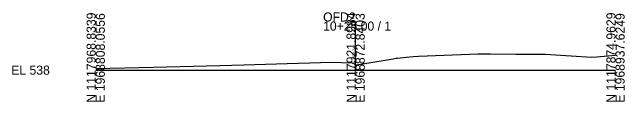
# Model space of a CAD drawing. Extents: x -26 to 163, y -10 to 2018.
# Drawn here: x -25.7 to 162.8, y -9.7 to 17.8 of the extents above; entities that cross this region are included whole.
import ezdxf

# ---------------------------------------------------------------- set-up
doc = ezdxf.new("R2010")
doc.units = 0
for name, color, linetype in [('RD_GPK_XS_Cell', 7, 'Continuous'), ('RD_XS_ExGround', 7, 'Continuous'), ('RD_XS_TX_Elev_EX', 7, 'Continuous')]:
    doc.layers.add(name, color=color, linetype=linetype)

msp = doc.modelspace()

# ---------------------------------------------------------------- linework, layer by layer
at = {"layer": 'RD_GPK_XS_Cell'}
for p, q in [((80, 0), (80, 14.92)), ((0, 0), (80, 0)), ((80, 0), (160, 0))]:
    msp.add_line(p, q, dxfattribs=at)
at = {"layer": 'RD_XS_ExGround'}
for p, q in [((92.89, 3.72), (95.58, 3.98)), ((95.58, 3.98), (97.74, 4.2)), ((97.74, 4.2), (99.39, 4.26)), ((99.39, 4.26), (117.73, 4.97)), ((117.73, 4.97), (121.49, 4.96)), ((121.49, 4.96), (129.28, 4.95)), ((129.28, 4.95), (131.76, 4.94)), ((131.76, 4.94), (132.93, 4.94)), ((132.93, 4.94), (133.7, 4.94)), ((133.7, 4.94), (138.3, 4.89)), ((138.3, 4.89), (146.35, 4.36)), ((146.35, 4.36), (152.6, 3.95)), ((152.6, 3.95), (154.22, 4.09)), ((154.22, 4.09), (160, 4.57)), ((45.54, 1.67), (62.35, 2.17)), ((62.35, 2.17), (65.95, 2.27)), ((65.95, 2.27), (72.46, 2.47)), ((72.46, 2.47), (78.96, 2.22)), ((78.96, 2.22), (80.12, 1.68)), ((80.12, 1.68), (82.87, 2.08)), ((82.87, 2.08), (91.52, 3.52)), ((91.52, 3.52), (92.45, 3.68)), ((92.45, 3.68), (92.89, 3.72)), ((0, 0.53), (17.8, 0.87)), ((17.8, 0.87), (38.19, 1.45)), ((38.19, 1.45), (45.54, 1.67))]:
    msp.add_line(p, q, dxfattribs=at)

# ---------------------------------------------------------------- texts
at = {"layer": 'RD_GPK_XS_Cell'}
for s, p in [('N 1117968.8339', (0, -10)), ('E 1968808.0556', (2.8, -10)), ('N 1117921.8984', (80, -10)), ('E 1968872.8403', (82.8, -10)), ('N 1117874.9629', (160, -10)), ('E 1968937.6249', (162.8, -10))]:
    msp.add_text(s, height=2.8, rotation=90, dxfattribs=at).set_placement(p)
for s, p in [('OFD2', (70, 14.92)), ('10+25.00 / 1', (70, 12.12)), ('EL 538', (-26, -1.4))]:
    msp.add_text(s, height=2.8, dxfattribs=at).set_placement(p)
at = {"layer": 'RD_XS_TX_Elev_EX'}
msp.add_text('539.74', height=0.8, rotation=90, dxfattribs=at).set_placement((79.9, 3.74))

doc.saveas('drawing.dxf')
